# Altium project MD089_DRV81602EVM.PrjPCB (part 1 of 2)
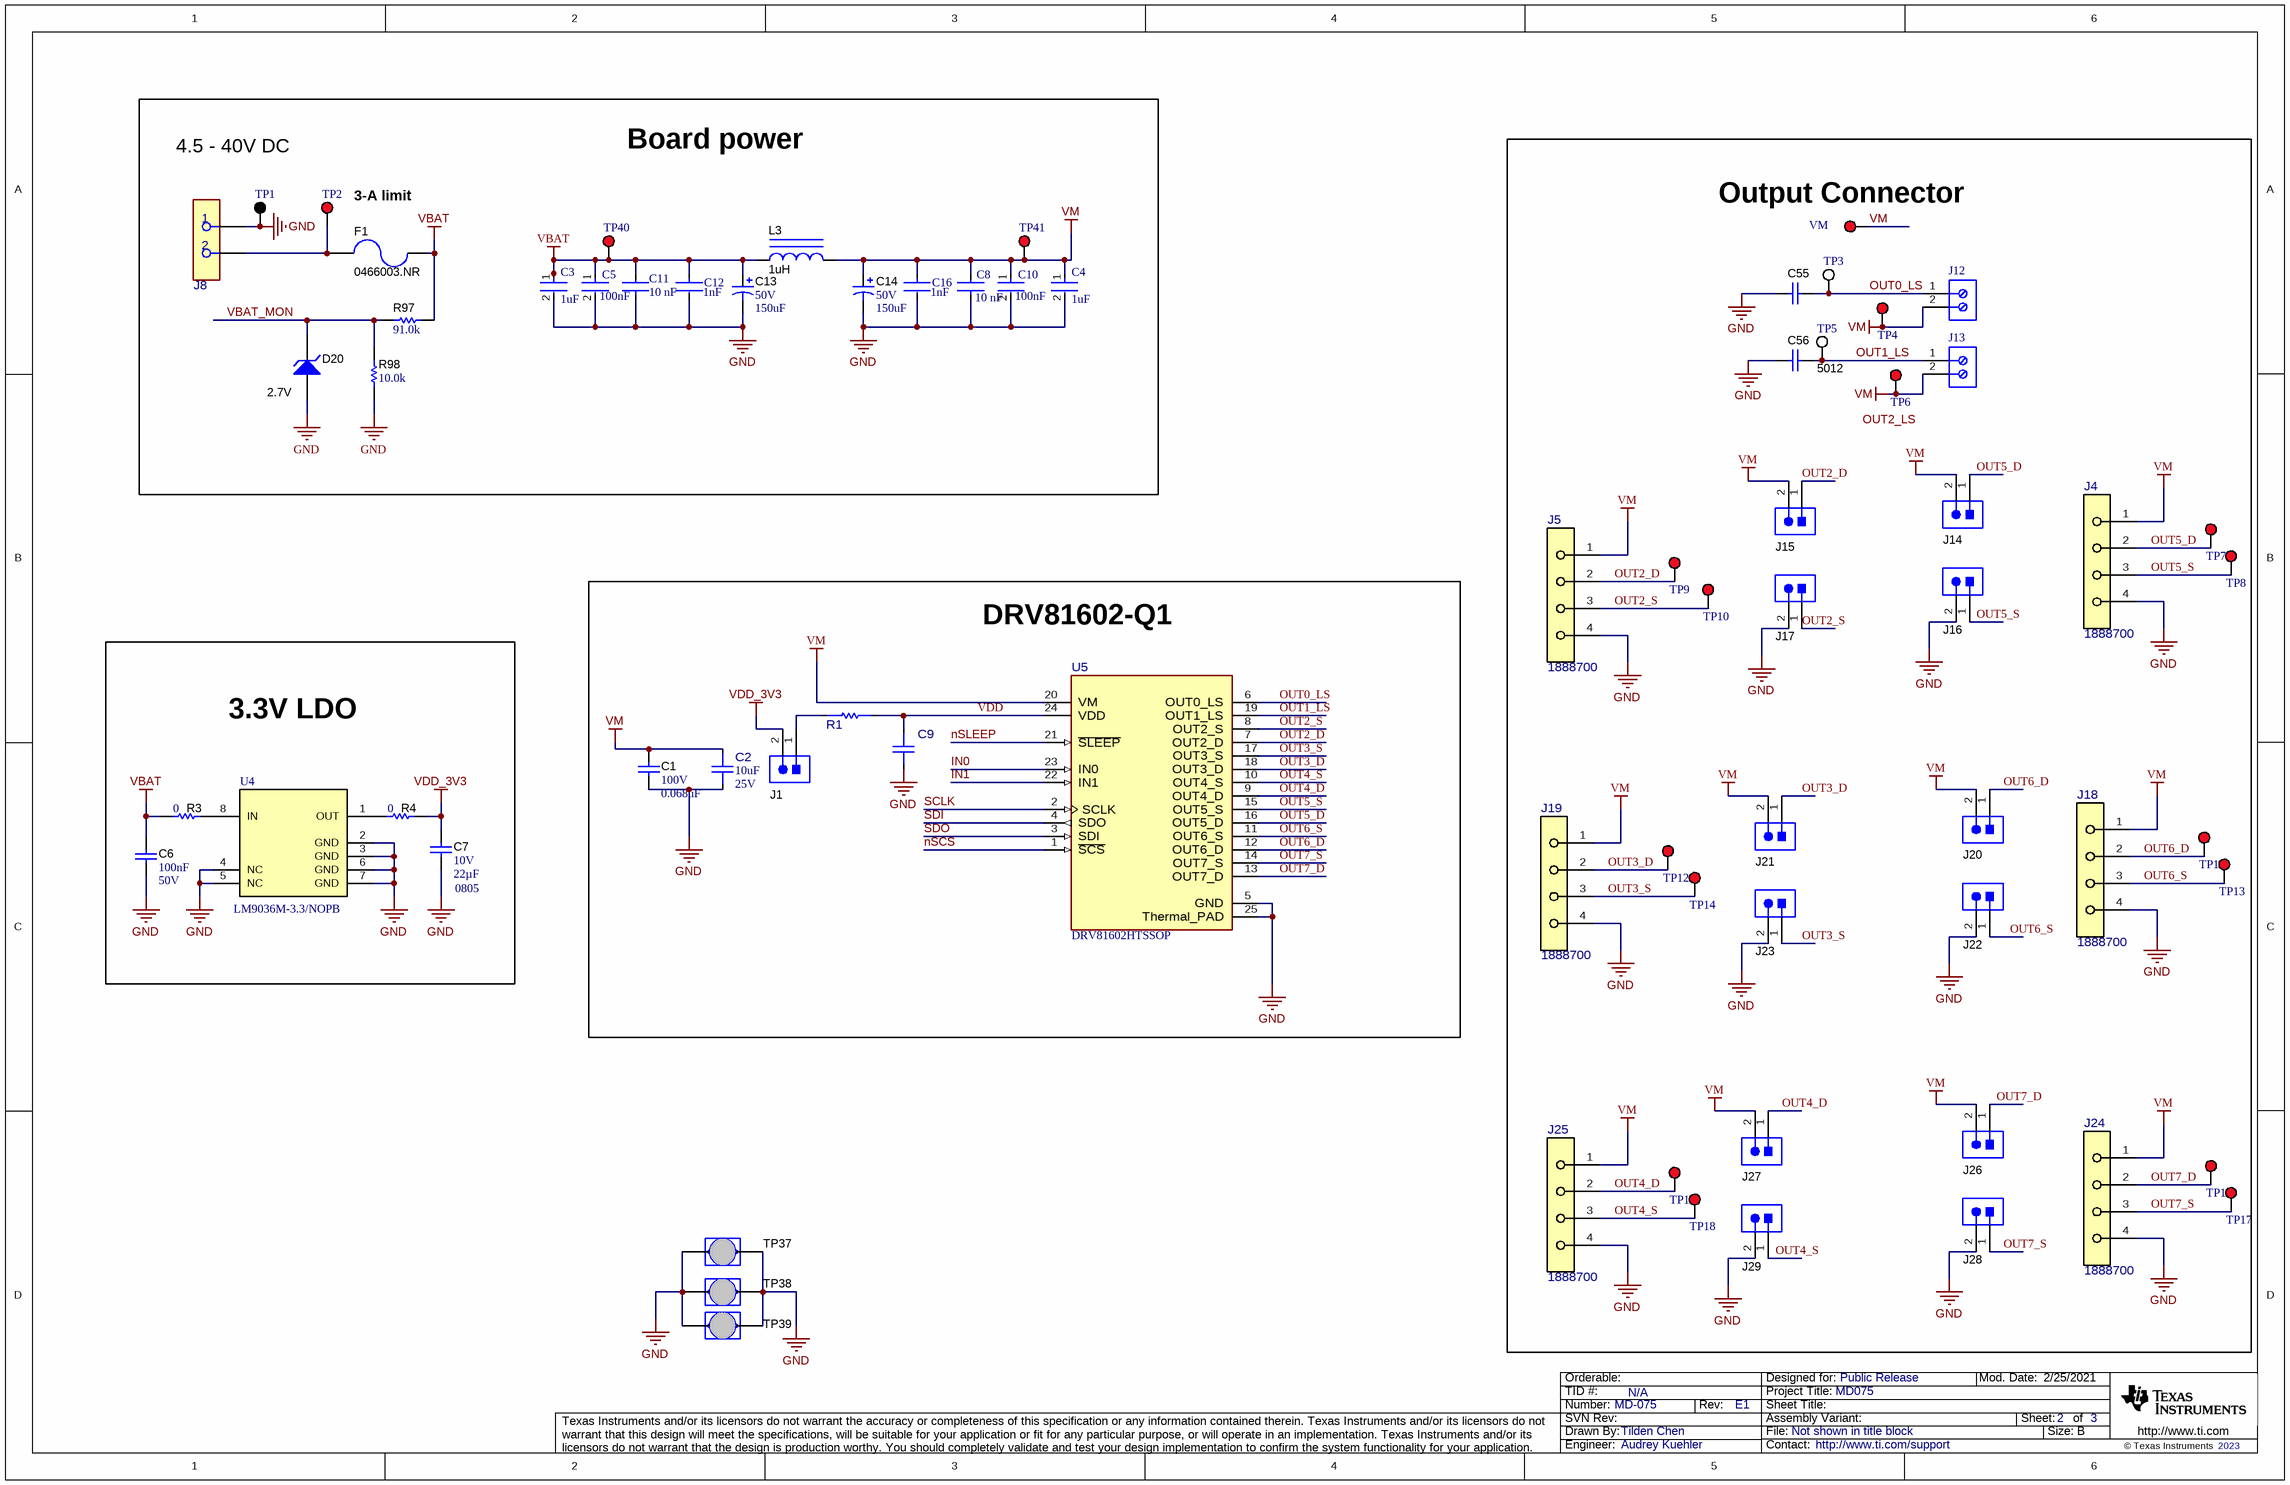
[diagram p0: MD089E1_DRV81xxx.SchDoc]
CopyrightYear: 2023; PCB_Layout: Audrey Kuehler; PCB_Rev: E1; PRJ_Customer: Public Release; PRJ_Engineer: Audrey Kuehler; PRJ_Number: MD-075; PRJ_Title: MD075; SCH_Rev: E1; TechSupport: http://www.ti.com/support; TID: N/A
4 sheets, 256 parts. Net scope: global (net labels, ports and power ports of the same name join across sheets).
Board file: DRV81602Q1_EVM-042624.PcbDoc
Sheets:
  MD089E1_DRV81xxx.SchDoc
  MD089E1_ezFET.SchDoc
  MD089E1_Hardware.SchDoc
  MD089E1_MCU.SchDoc

## Sheet MD089E1_DRV81xxx.SchDoc
size 431 x 279 mm; Date: Not shown in title block; ApprovedBy: Not shown in title block; CheckedBy: Not shown in title block; Author: Not shown in title block; CompanyName: Not shown in title block; DrawnBy: Tilden Chen; Engineer: Not shown in title block; Organization: Not shown in title block; Address1: Not shown in title block; Address2: Not shown in title block; Address3: Not shown in title block; Address4: Not shown in title block; DocumentNumber: 2; Revision: Use project parameter SCH_Rev; SheetNumber: 2; SheetTotal: 3; PageSetup: Record=PageOptions¦CenterHorizontal=True¦CenterVertical=True¦PrintScale=1.00¦XCorrection=1.00¦YCorrection=1.00¦PrintKind=0¦BorderSize=5000000¦LeftOffset=0¦BottomOffset=0¦Orientation=2¦PaperLength=1000¦PaperWidth=1000¦Scale=100¦PaperSource=15¦PrintQuality=600¦MediaType=1¦DitherType=10¦PaperKind=Letter¦PrintScaleMode=1

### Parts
C1  VDC_V: 100V  ValueDisplayed: 0.068uF  [1206]  (hidden comment: 12061C683KAT2A)
C2  ValueDisplayed: 10uF  VDC_V: 25V  [FP-ZRB18AR61E106ME01L_0603-MFG]  (hidden comment: ZRB18AR61E106ME01L)
C3  Capacitance: 1uF  [FP-0603-L_1_6_0_15-W_0_8-IPC_C]  (hidden comment: UMK107AB7105KA-T)
C4  Capacitance: 1uF  [FP-0603-L_1_6_0_15-W_0_8-IPC_C]  (hidden comment: UMK107AB7105KA-T)
C5  value 100nF  [FP-885012206095-MFG]  (hidden comment: 885012206095)
C6  Cap_F: 100nF  VDC_V: 50V  [0603]  (hidden comment: 885012206095)
C7  PackageReference: 0805  VDC_V: 10V  ValueDisplayed: 22µF  [0805_150]  (hidden comment: 885012107011)
C8  value 10 nF  [FP-CC0603-DA-MFG]  (hidden comment: CC0603KPX7R9BB103)
C9  885012205018  [FP-885012205018_0402-MFG]  (value not drawn)
C10  value 100nF  [FP-885012206095-MFG]  (hidden comment: 885012206095)
C11  value 10 nF  [FP-CC0603-DA-MFG]  (hidden comment: CC0603KPX7R9BB103)
C12  1nF  [FP-C0603C-CF-MFG]
C13  VDC_V: 50V  ValueDisplayed: 150uF  [SM_RADIAL_G]  (hidden comment: EEE-FK1H151P)
C14  VDC_V: 50V  ValueDisplayed: 150uF  [SM_RADIAL_G]  (hidden comment: EEE-FK1H151P)
C16  1nF  [FP-C0603C-CF-MFG]
C55  885012206114  [0603]  (value not drawn)
C56  885012206114  [0603]  (value not drawn)
D20  value 2.7V  [SOD-123]  (hidden comment: MMSZ4682-E3-08)
F1  0466003.NR  [1206]
J1  HTSW-102-07-G-S  [Samtec_HTSW-102-07-G-S]  (value not drawn)
J4  1888700  [FP-1888700_HDR4-MFG]
J5  1888700  [FP-1888700_HDR4-MFG]
J8  691250610002  [FP-691250610002_CONN_TERM_BLOCK2-MFG]  (value not drawn)
J12  691101710002  [691101710002]  (value not drawn)
J13  691101710002  [691101710002]  (value not drawn)
J14  HTSW-102-07-G-S  [Samtec_HTSW-102-07-G-S]  (value not drawn)
J15  HTSW-102-07-G-S  [Samtec_HTSW-102-07-G-S]  (value not drawn)
J16  HTSW-102-07-G-S  [Samtec_HTSW-102-07-G-S]  (value not drawn)
J17  HTSW-102-07-G-S  [Samtec_HTSW-102-07-G-S]  (value not drawn)
J18  1888700  [FP-1888700_HDR4-MFG]
J19  1888700  [FP-1888700_HDR4-MFG]
J20  HTSW-102-07-G-S  [Samtec_HTSW-102-07-G-S]  (value not drawn)
J21  HTSW-102-07-G-S  [Samtec_HTSW-102-07-G-S]  (value not drawn)
J22  HTSW-102-07-G-S  [Samtec_HTSW-102-07-G-S]  (value not drawn)
J23  HTSW-102-07-G-S  [Samtec_HTSW-102-07-G-S]  (value not drawn)
J24  1888700  [FP-1888700_HDR4-MFG]
J25  1888700  [FP-1888700_HDR4-MFG]
J26  HTSW-102-07-G-S  [Samtec_HTSW-102-07-G-S]  (value not drawn)
J27  HTSW-102-07-G-S  [Samtec_HTSW-102-07-G-S]  (value not drawn)
J28  HTSW-102-07-G-S  [Samtec_HTSW-102-07-G-S]  (value not drawn)
J29  HTSW-102-07-G-S  [Samtec_HTSW-102-07-G-S]  (value not drawn)
L3  ValueDisplayed: 1uH  [WE-HCC_1210]  (hidden comment: 7443320100)
R1  SG73S1JTTD101J  [FP-SG73S1JTTD101J_0603-MFG]  (value not drawn)
R3  value 0  [0603L]  (hidden comment: Resistor)
R4  value 0  [0603L]  (hidden comment: Resistor)
R97  ValueDisplayed: 91.0k  [0603L]  (hidden comment: RG1608P-913-B-T5)
R98  ValueDisplayed: 10.0k  [0603L]  (hidden comment: RG1608P-103-B-T5)
TP1  5011  [Keystone5011]  (value not drawn)
TP2  5010  [Keystone5010]  (value not drawn)
TP3  5012  [Keystone5012]  (value not drawn)
TP4  5010  [Keystone5010]  (value not drawn)
TP5  5012  [Keystone5012]
TP6  5010  [Keystone5010]  (value not drawn)
TP7  5010  [Keystone5010]  (value not drawn)
TP8  5010  [Keystone5010]  (value not drawn)
TP9  5010  [Keystone5010]  (value not drawn)
TP10  5010  [Keystone5010]  (value not drawn)
TP11  5010  [Keystone5010]  (value not drawn)
TP12  5010  [Keystone5010]  (value not drawn)
TP13  5010  [Keystone5010]  (value not drawn)
TP14  5010  [Keystone5010]  (value not drawn)
TP15  5010  [Keystone5010]  (value not drawn)
TP16  5010  [Keystone5010]  (value not drawn)
TP17  5010  [Keystone5010]  (value not drawn)
TP18  5010  [Keystone5010]  (value not drawn)
TP37  Jumper_2p  [Harwin_D3082-05]  (value not drawn)
TP38  Jumper_2p  [Harwin_D3082-05]  (value not drawn)
TP39  Jumper_2p  [Harwin_D3082-05]  (value not drawn)
TP40  5010  [Keystone5010]  (value not drawn)
TP41  5010  [Keystone5010]  (value not drawn)
U4  LM9036M-3.3/NOPB  [D0008A_N]
U5  DRV81602HTSSOP  [PWP0024T-MFG]
VM  5010  [Keystone5010]  (value not drawn)

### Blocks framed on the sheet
Board power: C3-C5 C8 C10-C14 C16 D20 F1 J8 L3 R97 R98 TP1 TP2 TP40 TP41
Output Connector: C55 C56 J4 J5 J12-J29 TP3-TP18 VM
DRV81602-Q1: C1 C2 C9 J1 R1 U5
3.3V LDO: C6 C7 R3 R4 U4

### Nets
GND: C1.2 C2.2 C3.2 C4.2 C5.2 C6.2 C7.2 C8.1 C9.2 C10.2 C11.1 C12.2 C13.2(-) C14.2(-) C16.2 C55.2 C56.2 D20.2(A) J4.4 J5.4 J8.1 J16.2 J17.2 J18.4 J19.4 J22.2 J23.2 J24.4 J25.4 J28.2 J29.2 R98.1 TP1.1 TP37.1 TP37.2 TP38.1 TP38.2 TP39.1 TP39.2 U4.2(GND) U4.3(GND) U4.4(NC) U4.5(NC) U4.6(GND) U4.7(GND) U5.5(GND) U5.25(Thermal_PAD)
VBAT: C3.1 C5.1 C6.1 C11.2 C12.1 C13.1(+) F1.1 L3.1 R3.2 R97.2 TP40.1  [project net VS]
VDD_3V3: C7.1 J1.2 R4.1
VM: C1.1 C2.1 C4.1 C8.2 C10.1 C14.1(+) C16.1 J4.1 J5.1 J12.2 J13.2 J14.2 J15.2 J18.1 J19.1 J20.2 J21.2 J24.1 J25.1 J26.2 J27.2 L3.2 TP4.1 TP6.1 TP41.1 U5.20(VM) VM.1
IN0: U5.23(IN0)
IN1: U5.22(IN1)
nSCS: U5.1(~{SCS})
nSLEEP: U5.21(~{SLEEP})
OUT0_LS: C55.1 J12.1 TP3.1 U5.6(OUT0_LS)
OUT1_LS: C56.1 J13.1 TP5.1 U5.19(OUT1_LS)
OUT2_D: J5.2 J15.1 TP9.1 U5.7(OUT2_D)
OUT2_S: J5.3 J17.1 TP10.1 U5.8(OUT2_S)
OUT3_D: J19.2 J21.1 TP12.1 U5.18(OUT3_D)
OUT3_S: J19.3 J23.1 TP14.1 U5.17(OUT3_S)
OUT4_D: J25.2 J27.1 TP16.1 U5.9(OUT4_D)
OUT4_S: J25.3 J29.1 TP18.1 U5.10(OUT4_S)
OUT5_D: J4.2 J14.1 TP7.1 U5.16(OUT5_D)
OUT5_S: J4.3 J16.1 TP8.1 U5.15(OUT5_S)
OUT6_D: J18.2 J20.1 TP11.1 U5.12(OUT6_D)
OUT6_S: J18.3 J22.1 TP13.1 U5.11(OUT6_S)
OUT7_D: J24.2 J26.1 TP15.1 U5.13(OUT7_D)
OUT7_S: J24.3 J28.1 TP17.1 U5.14(OUT7_S)
SCLK: U5.2(SCLK)
SDI: U5.4(SDO)
SDO: U5.3(SDI)
VBAT_MON: D20.1(K) R97.1 R98.2
VDD: C9.1 R1.2 U5.24(VDD)
NetF1_2: F1.2 J8.2 TP2.1
NetJ1_1: J1.1 R1.1
NetR3_1: R3.1 U4.8(IN)
NetR4_2: R4.2 U4.1(OUT)

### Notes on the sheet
- 4.5 - 40V DC
- 3-A limit
- Labels drawn without touching a wire or pin: OUT2_LS

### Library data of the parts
C1 = CMP-0008507-2: CAP, CERM, 0.068 uF, 100 V, +/- 10%, X7R, 1206; Manufacturer: AVX; TaMin_C: -55°C; ESR_ohm: 0.045; Polarized: N; SizeAreaWB_mm2: 10.92; Value1: 0.045 ohm; U/M: EA; TaMax_C: 125°C; SizeZ_mm: 1.35; SizeX_mm: 3.2; SizeY_mm: 1.6; SizeArea_mm2: 5.12; Cap_F: 68nF; AEC Category: Q200
C2 = CMP-0094458-1: 10µF ±20% 25V Ceramic Capacitor X5R 0603 (1608 Metric); Manufacturer: Murata Electronics; SizeZ_mm: 1.2mm; AEC Qualified: No
C3 C4 = CMP-2000-07531-4: Ceramic Capacitor General Use 1uF ±10% 50V X7R 0603
C5 C10 = CMP-207839-000004-1: CAP CER 0.1UF 50V X7R 0603; Tolerance: 10%
C6 = CMP-0006837-4: CAP, CERM, 0.1 uF, 50 V, +/- 10%, X7R, 0603; Manufacturer: Wurth Elektronik; TaMin_C: -55°C; Polarized: N; SizeAreaWB_mm2: 4.68; Value1: Unknown; U/M: EA; Value: 0.1uF; TaMax_C: 125°C; SizeZ_mm: 1; SizeX_mm: 1.6; SizeY_mm: 0.8; SizeArea_mm2: 1.28; AEC Category: Q200
C7 = CMP-0078153-1: CAP, CERM, 22 µF, 10 V,+/- 20%, X5R, 0805; Manufacturer: Wurth Elektronik; TaMin_C: -55°C; Polarized: N; SizeAreaWB_mm2: 6.75; U/M: EA; Value: 22uF; TaMax_C: 85°C; SizeZ_mm: 1.5; SizeX_mm: 2; SizeY_mm: 1.25; SizeArea_mm2: 2.5; AEC Category: Q200
C8 C11 = CMP-1035-02321-3: CAP CER 10000PF 50V X7R 0603; Manufacturer: YAGEO; Alternative PartNumber: 885382206002; Alternative Manufacturer: Wurth Elektronik; Tolerance: 0.1; Material: Ceramic; Temperature Coefficient: 15%
C9 = CMP-0090362-1: 0.1µF ±10% 10V Ceramic Capacitor X7R 0402 (1005 Metric); Manufacturer: Wurth Electronics; AEC Qualified: No; Value: 100nF; SizeZ_mm: 0.55mm; ValueDisplayed: 100000pF; TempCo: 15%
C12 C16 = CMP-03020-030804-1: CAP CER 1000PF 50V X7R 0603; Manufacturer Part Number: C0603C102J5RACAUTO; Manufacturer: KEMET; Alternate PartNumber: 885012206083; Alternate Manufacturer: Wurth Elektronik; Material: Ceramic; Value: 1,000 pF; Temperature Coefficient: 30ppm/°C; Automotive Grade: Grade 1; Tolerance: 0.05
C13 C14 = CMP-0011178-2: CAP, AL, 150 uF, 50 V, +/- 20%, 0.18 ohm, AEC-Q200 Grade 2, SMD; Manufacturer: Panasonic; Alternate Manufacturer: Wurth Elektronik; Alternate PartNumber: 865080657017; TaMin_C: -55°C; ESR_ohm: 0.18; Polarized: Y; SizeAreaWB_mm2: 172.2; U/M: EA; Value: 150uF; TaMax_C: 105°C; SizeZ_mm: 10.2; SizeX_mm: 12; SizeY_mm: 10.3; Cap_Case: G; SizeArea_mm2: 123.6; CompType: Capacitor; Cap_F: 150µF; IRMS_A: 670mA; AEC Grade: 2; AEC Category: Q200
C55 C56 = CMP-0079993-1: CAP, CERM, 0.01 µF, 100 V,+/- 10%, X7R, 0603; Manufacturer: Wurth Elektronik; TaMin_C: -55°C; Polarized: N; SizeAreaWB_mm2: 4.68; U/M: EA; Value: 0.01uF; TaMax_C: 105°C; SizeZ_mm: 1; SizeX_mm: 1.6; SizeY_mm: 0.8; Value2: 100V; SizeArea_mm2: 1.28; Cap_F: 10nF; AEC Category: Q200; ValueDisplayed: 0.01µF
D20 = CMP-0077592-3: Diode, Zener, 2.7 V, 500 mW, SOD-123; Manufacturer: Vishay-Semiconductor; AEC Category: Q101; AEC Qualified: N; SizeAreaWB_mm2: 13.095; SizeY_mm: 1.7; SizeX_mm: 3.85; Value1: 0.5W; SizeArea_mm2: 6.545; SizeZ_mm: 1.35; RJA_CperW: 340; Power_W: 500mW
F1 = CMP-0084439-1: Fuse, 3 A, 32VAC/VDC, SMD; Manufacturer: Littelfuse; VAC_V: 32V; Rtyp_Ohm: 0.019; Interrupt_AC: 50A; MeltingTyp: 0.576; SizeX_mm: 3.2; Fuse Technology: Board Mount; Irating_A: 3A; SizeAreaWB_mm2: 10.92; TaMin_C: -55°C; Fuse Speed: Fast; SizeArea_mm2: 5.12; SizeY_mm: 1.6; SizeZ_mm: 1.35; TaMax_C: 90°C
J1 J14-J17 J20-J23 J26-J29 = CMP-0075483-1: Header, 100mil, 2x1, Gold, TH; Manufacturer: Samtec; Green_REACh: Passed; CT: False; Green_Lifecycle: Active; CNHeader: True
J4 J5 J18 J19 J24 J25 = CMP-0086377-1: Conn; Term Blk; PCB; Screw; 4; 5.08 mm; Front; 24-14 AWG; 16 A; 250 V; Solder; Manufacturer: Phoenix Contact; ContactFinish: Tin; Current_A: 16A; Row_Count: 1; Voltage_V: 400V
J8 = CMP-0093233-2: 2 Position Wire to Board Terminal Block Horizontal with Board 0.250" (6.35mm) Through Hole; Manufacturer: Wurth Electronics; Current_A: 32A; Conn Gender: Female; Row_Count: 1; ContactFinish: Zinc; SizeZ_mm: 21.6mm; Max Wire Gauge: 10; Min Wire Gauge: 30; Voltage_V: 450V; AEC Qualified: No; Is Female: yes
J12 J13 = CMP-1502-03256-1: Series 101 - 5.00 mm Horizontal Entry Modular with Pressure Clamp WR-TBL, 2 pin; Manufacturer: Wurth Elektronik; Pin Number: 2; Pitch: 5.00mm
L3 = CMP-0063986-1: Inductor, Shielded Drum Core, Ferrite, 1 uH, 24 A, 0.0012 ohm, SMD; Manufacturer: Wurth Elektronik; Isat: 32A @ 30% inductance drop; Irms: 24A @ 50C rise; Green_Lifecycle: Active; SizeAreaWB_mm2: 188.94; DCR_ohm: 1.2m; Green_REACh: Passed; Value: 1uH; Imax_A: 24A; SizeZ_mm: 10; SizeX_mm: 12.1; SizeY_mm: 11.4; SizeArea_mm2: 137.94; Ind_H: 1µH; AEC Category: Q200
R1 = CMP-0095262-1: 100 Ohms ±5% 0.2W, 1/5W Chip Resistor 0603 (1608 Metric) Automotive AEC-Q200, Moisture Resistant, Pulse Withstanding Thick Film; Manufacturer: KOA Speer; AEC Qualified: Yes; Value: 100; AEC Grade: Grade 0; VDC_V: 150V; TaMax_C: +70°C; TempCo: 100ppm/°C; Power_W: 200mW; SizeZ_mm: 0.55mm
R3 R4 = CMP-0025697-4: RES, 0, 5%, 0.1 W, AEC-Q200 Grade 0, 0603; PartNumber: CRCW06030000Z0EA; Manufacturer: Vishay-Dale; Value_Code: 0000; Power_W: 100mW; Value2: 0.1W; VDC_V: 75V; TempCo: 200 ppm/C; EIA_Code: E24; AEC Category: Q200; AEC Qualified: Y; SizeArea_mm2: 1.28; SizeX_mm: 1.6; SizeY_mm: 0.8; SizeZ_mm: 1
R97 = CMP-0023620-3: RES, 91.0 k, 0.1%, 0.1 W, 0603; Manufacturer: Susumu Co Ltd; Power_W: 100mW; TempCo: 25 ppm/C; Value_Code: 91k0; U/M: EA; Value: 91.0k; Res_ohm: 91k; SizeX_mm: 1.6; SizeY_mm: 0.8; SizeZ_mm: 1; Value2: 0.1W; SizeArea_mm2: 1.28; VDC_V: 75V; AEC Category: Q200
R98 = CMP-0023404-3: RES, 10.0 k, 0.1%, 0.1 W, 0603; Manufacturer: Susumu Co Ltd; Power_W: 100mW; TempCo: 25 ppm/C; Value_Code: 10k0; U/M: EA; Value: 10.0k; EIA_Code: E192; Res_ohm: 10k; SizeX_mm: 1.6; SizeY_mm: 0.8; SizeZ_mm: 1; Value2: 0.1W; SizeArea_mm2: 1.28; VDC_V: 75V; AEC Category: Q200
TP1 = CMP-0055148-2: Test Point, Multipurpose, Black, TH; Manufacturer: Keystone Electronics; CNHeader: FALSE; Green_Lifecycle: Active; Green_REACh: Passed; ContactFinish: Silver; CT: TRUE
TP2 TP4 TP6-TP18 VM = CMP-0055147-2: Test Point, Multipurpose, Red, TH; Manufacturer: Keystone Electronics; CNHeader: FALSE; Green_Lifecycle: Active; Green_REACh: Passed; ContactFinish: Silver; CT: TRUE
TP3 TP5 = CMP-0055149-2: Test Point, Multipurpose, White, TH; Manufacturer: Keystone Electronics; ContactFinish: Silver; CT: TRUE; CNHeader: FALSE; Green_Lifecycle: Active; Green_REACh: Passed
TP37-TP39 = CMP-0075110-1: 1mm Uninsulated Shorting Plug, 10.16mm spacing, TH; Manufacturer: Harwin; PartNumber: D3082-05; CompType: Jumper Wire; CNHeader: False; Green_Lifecycle: Active; Green_REACh: Passed
TP40 TP41 = CMP-0055147-1: Test Point, Multipurpose, Red, TH; Manufacturer: Keystone; CNHeader: FALSE; Green_Lifecycle: Active; Green_REACh: Passed; ContactFinish: Silver; CT: TRUE
U4 = CMP-0070570-1: Ultra-Low Quiescent Current Voltage Regulator, 8-pin Narrow SOIC, Pb-Free; Manufacturer: Texas Instruments; PackageTopMarking: NSZXTT*LM903*6M-3; PowerWise: N; CompType: LDO IC
U5 = CMP-0120420-1: 8-channel Configurable Low-side and High-side Driver for Automotive Relay, Lighting and Motor Control; Manufacturer: Texas Instruments; SizeZ_mm: 1.2mm; AEC Qualified: No; Max Supply Voltage: 40V; Min Supply Voltage: 3V; Number Of Outputs: 8; Standoff Height: 0.05mm; TaMax_C: +125°C; TaMin_C: -40°C; TJmax_C: +150°C

## Sheet MD089E1_ezFET.SchDoc
size 431 x 279 mm; Date: Not shown in title block; ApprovedBy: Not shown in title block; CheckedBy: Not shown in title block; Author: Not shown in title block; CompanyName: Not shown in title block; DrawnBy: Murugavel Raju; Engineer: Not shown in title block; Organization: Not shown in title block; Address1: Not shown in title block; Address2: Not shown in title block; Address3: Not shown in title block; Address4: Not shown in title block; DocumentNumber: 1; Revision: Use project parameter SCH_Rev; SheetNumber: 1; SheetTotal: 3; PageSetup: Record=PageOptions¦CenterHorizontal=True¦CenterVertical=True¦PrintScale=1.00¦XCorrection=1.00¦YCorrection=1.00¦PrintKind=0¦BorderSize=5000000¦LeftOffset=0¦BottomOffset=0¦Orientation=2¦PaperLength=1000¦PaperWidth=1000¦Scale=100¦PaperSource=15¦PrintQuality=600¦MediaType=1¦DitherType=10¦PaperKind=Letter¦PrintScaleMode=1
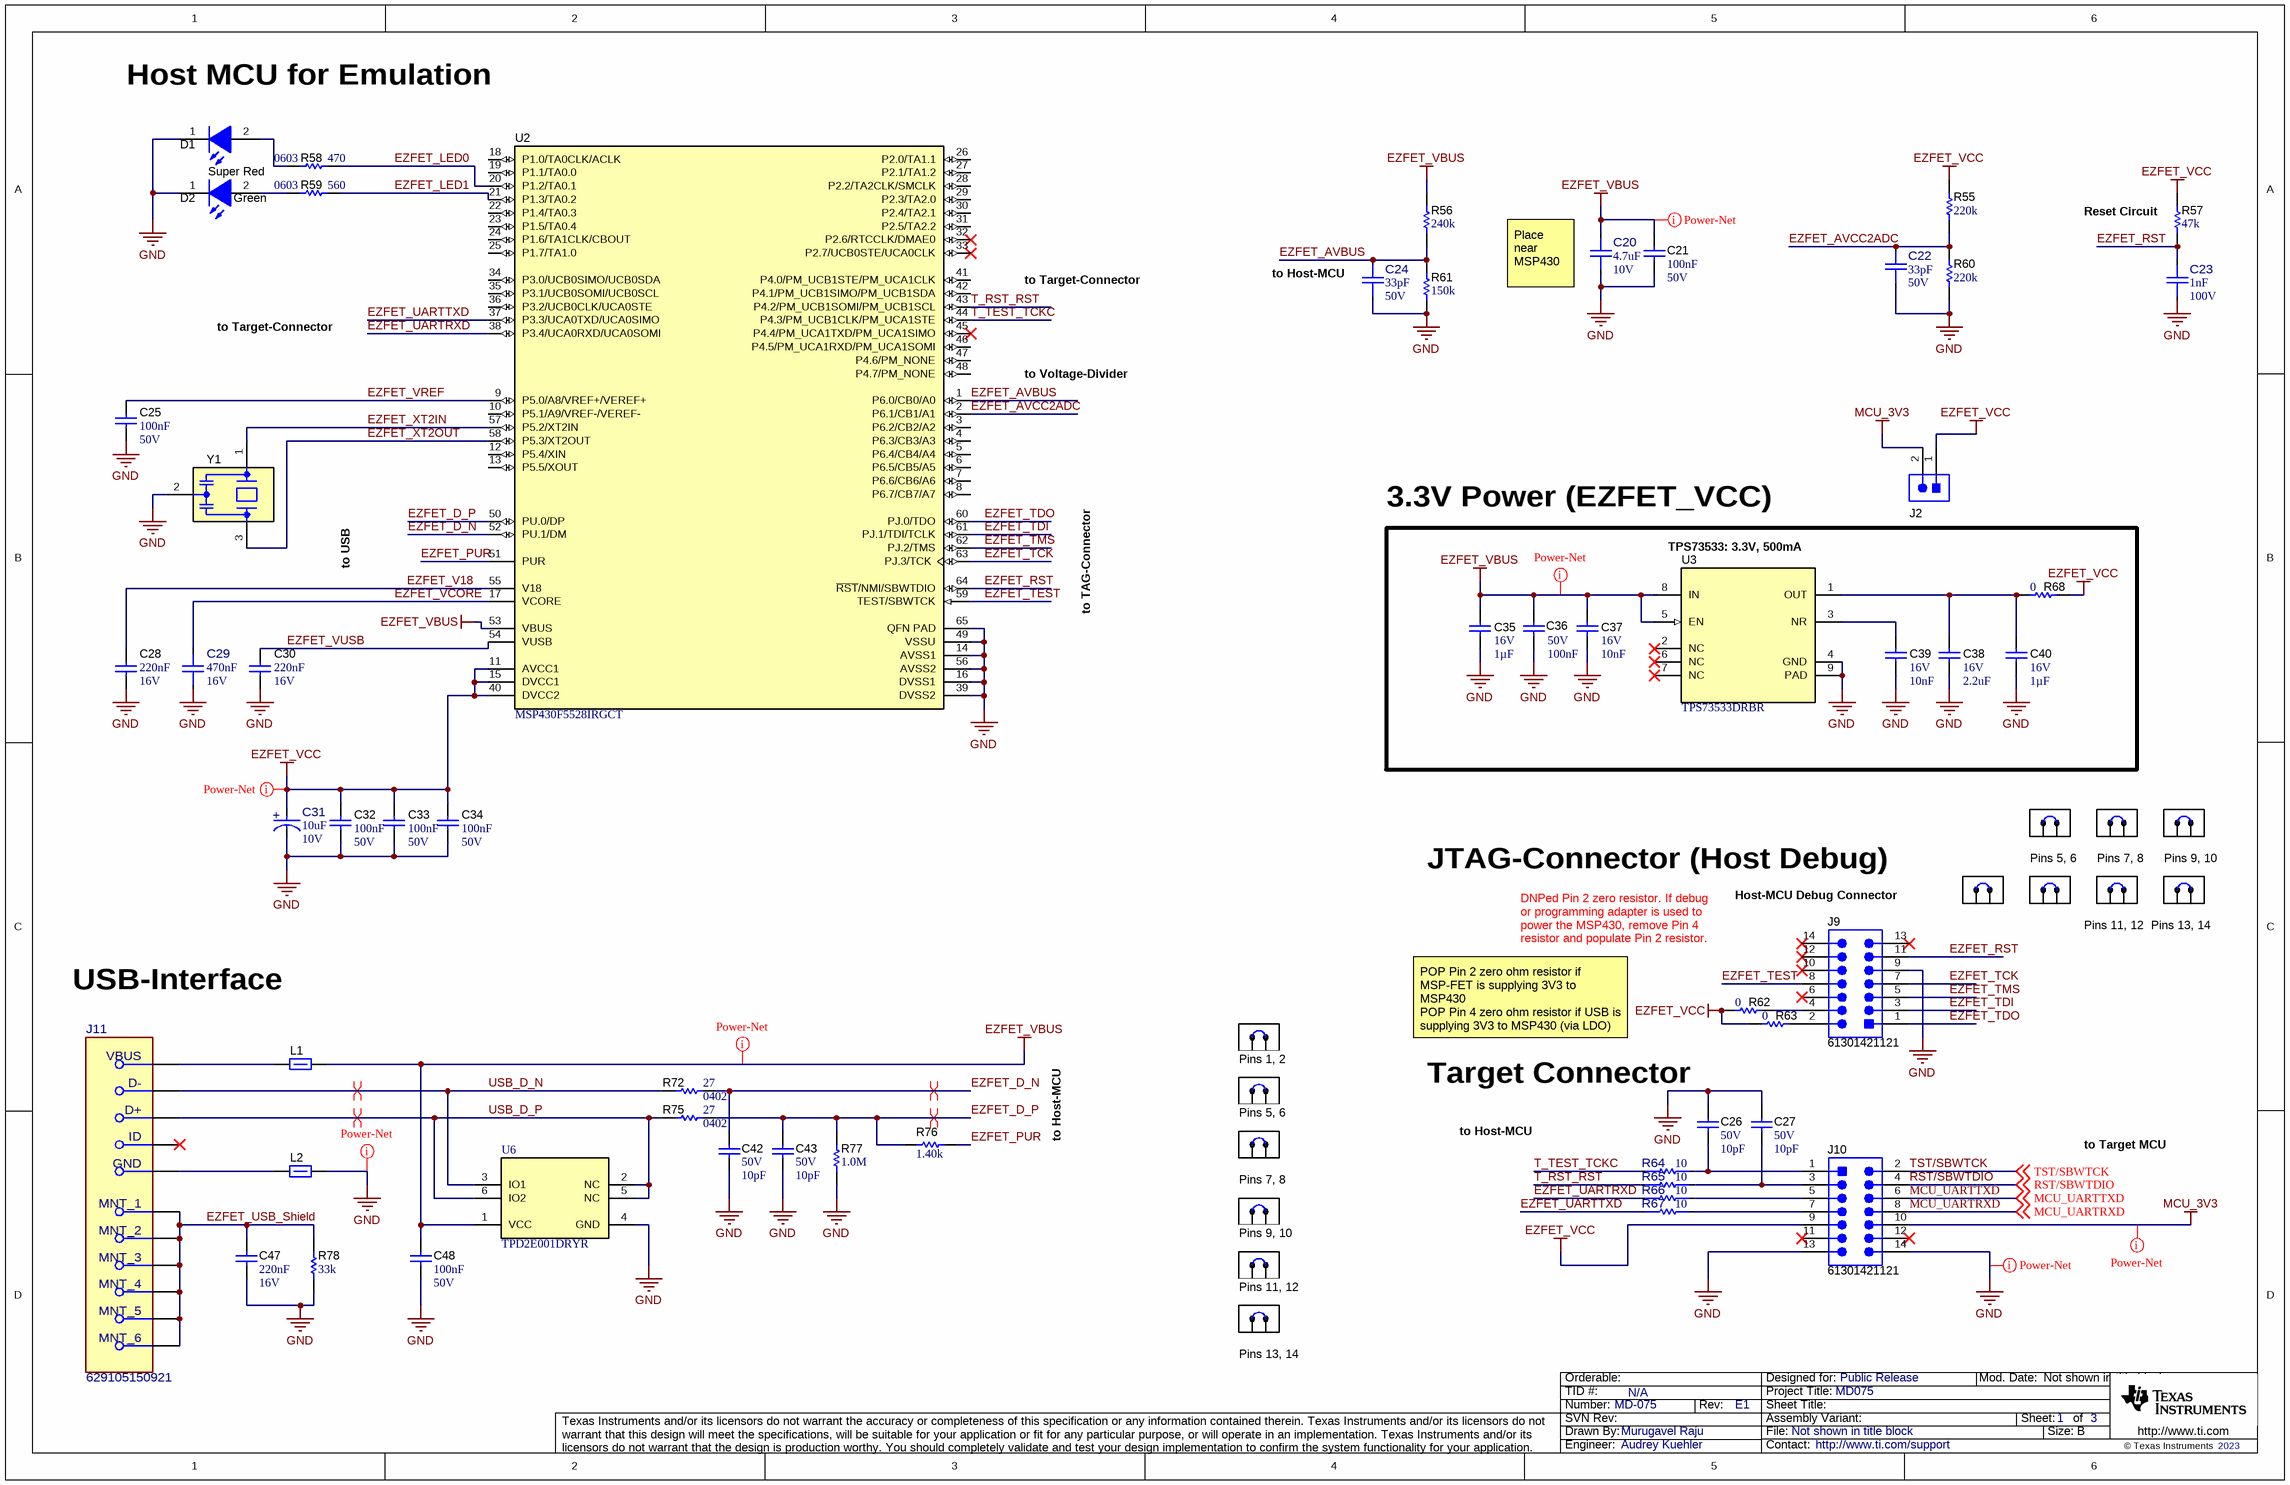
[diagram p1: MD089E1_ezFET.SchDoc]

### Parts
C20  ValueDisplayed: 4.7uF  VDC_V: 10V  [FP-885012106012_0603-MFG]  (hidden comment: 885012106012)
C21  Cap_F: 100nF  VDC_V: 50V  [0603]  (hidden comment: 885012206095)
C22  ValueDisplayed: 33pF  VDC_V: 50V  [FP-885012005058_0402-MFG]  (hidden comment: 885012005058)
C23  ValueDisplayed: 1nF  VDC_V: 100V  [FP-885012006085_0603-MFG]  (hidden comment: 885012006085)
C24  ValueDisplayed: 33pF  VDC_V: 50V  [FP-885012005058_0402-MFG]  (hidden comment: 885012005058)
C25  Cap_F: 100nF  VDC_V: 50V  [0603]  (hidden comment: 885012206095)
C26  VDC_V: 50V  ValueDisplayed: 10pF  [0402]  (hidden comment: 885012005055)
C27  VDC_V: 50V  ValueDisplayed: 10pF  [0402]  (hidden comment: 885012005055)
C28  Cap_F: 220nF  VDC_V: 16V  [0603L]  (hidden comment: 885012206048)
C29  VDC_V: 16V  Cap_F: 470nF  [FP-885012206050_0603-MFG]  (hidden comment: 885012206050)
C30  Cap_F: 220nF  VDC_V: 16V  [0603L]  (hidden comment: 885012206048)
C31  ValueDisplayed: 10uF  VDC_V: 10V  [FP-875105240001_SMT_CAP_4MM3_4MM3-MFG]  (hidden comment: 875105240001)
C32  Cap_F: 100nF  VDC_V: 50V  [0603]  (hidden comment: 885012206095)
C33  Cap_F: 100nF  VDC_V: 50V  [0603]  (hidden comment: 885012206095)
C34  Cap_F: 100nF  VDC_V: 50V  [0603]  (hidden comment: 885012206095)
C35  Cap_F: 1µF  VDC_V: 16V  [0603]  (hidden comment: 885012206052)
C36  Cap_F: 100nF  VDC_V: 50V  [0603]  (hidden comment: 885012206095)
C37  Cap_F: 10nF  VDC_V: 16V  [0603]  (hidden comment: 885012206040)
C38  VDC_V: 16V  ValueDisplayed: 2.2uF  [0603]  (hidden comment: 885012106018)
C39  Cap_F: 10nF  VDC_V: 16V  [0603]  (hidden comment: 885012206040)
C40  Cap_F: 1µF  VDC_V: 16V  [0603]  (hidden comment: 885012206052)
C42  VDC_V: 50V  ValueDisplayed: 10pF  [0402]  (hidden comment: 885012005055)
C43  VDC_V: 50V  ValueDisplayed: 10pF  [0402]  (hidden comment: 885012005055)
C47  Cap_F: 220nF  VDC_V: 16V  [0603L]  (hidden comment: 885012206048)
C48  Cap_F: 100nF  VDC_V: 50V  [0603]  (hidden comment: 885012206095)
D1  value Super Red  [WL-SMCW_RED]  (hidden comment: 150060SS75000)
D2  value Green  [WL-SMCW_GREEN]  (hidden comment: 150060VS75000)
J2  HTSW-102-07-G-S  [Samtec_HTSW-102-07-G-S]  (value not drawn)
J9  61301421121  [Wurth_61301421121]
J10  61301421121  [Wurth_61301421121]
J11  629105150921  [FP-629105150921_CONN_PTH_USB_8MM0_5MM6-MFG]
L1  742792621  [0603L]  (value not drawn)
L2  742792621  [0603L]  (value not drawn)
R55  ValueDisplayed: 220k  [0402]  (hidden comment: RC0402FR-07220KL)
R56  ValueDisplayed: 240k  [0402]  (hidden comment: CRCW0402240KFKED)
R57  ValueDisplayed: 47k  [0402]  (hidden comment: CRCW040247K0JNED)
R58  ValueDisplayed: 470  [0603]  (hidden comment: RC0603JR-07470RL)
R59  ValueDisplayed: 560  [0603]  (hidden comment: RC0603JR-07560RL)
R60  ValueDisplayed: 220k  [0402]  (hidden comment: RC0402FR-07220KL)
R61  ValueDisplayed: 150k  [0402]  (hidden comment: CRCW0402150KFKED)
R62  value 0  [0603L]  (hidden comment: Resistor)
R63  value 0  [0603L]  (hidden comment: Resistor)
R64  value 10  [FP-560050310009_0402-MFG]  (hidden comment: 560050310009)
R65  value 10  [FP-560050310009_0402-MFG]  (hidden comment: 560050310009)
R66  value 10  [FP-560050310009_0402-MFG]  (hidden comment: 560050310009)
R67  value 10  [FP-560050310009_0402-MFG]  (hidden comment: 560050310009)
R68  value 0  [0603L]  (hidden comment: Resistor)
R72  PackageReference: 0402  ValueDisplayed: 27  [0402L]  (hidden comment: CRCW040227R0JNED)
R75  PackageReference: 0402  ValueDisplayed: 27  [0402L]  (hidden comment: CRCW040227R0JNED)
R76  ValueDisplayed: 1.40k  [0402L]  (hidden comment: CRCW04021K40FKED)
R77  ValueDisplayed: 1.0M  [0402L]  (hidden comment: CRCW04021M00JNED)
R78  ValueDisplayed: 33k  [0402S]  (hidden comment: CRCW040233K0JNED)
SH-J22  60900213421  [Wurth_60900213421]  (value not drawn)
SH-J23  60900213421  [Wurth_60900213421]  (value not drawn)
SH-J24  60900213421  [Wurth_60900213421]  (value not drawn)
SH-J25  60900213421  [Wurth_60900213421]  (value not drawn)
SH-J26  60900213421  [Wurth_60900213421]  (value not drawn)
SH-J27  60900213421  [Wurth_60900213421]  (value not drawn)
SH-J28  60900213421  [Wurth_60900213421]  (value not drawn)
SH-J29  60900213421  [Wurth_60900213421]  (value not drawn)
SH-J31  60900213421  [Wurth_60900213421]  (value not drawn)
SH-J32  60900213421  [Wurth_60900213421]  (value not drawn)
SH-J33  60900213421  [Wurth_60900213421]  (value not drawn)
SH-J34  60900213421  [Wurth_60900213421]  (value not drawn)
SH-J35  60900213421  [Wurth_60900213421]  (value not drawn)
U2  MSP430F5528IRGCT  [RGC0064B]
U3  TPS73533DRBR  [DRB0008A]
U6  TPD2E001DRYR  [DRY0006A]
Y1  CSTNR4M00GH5L000R0  [MuRata_CSTNR]  (value not drawn)

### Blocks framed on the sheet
3.3V Power (EZFET_VCC): C35-C40 R68 U3

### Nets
EZFET_VBUS: C20.2 C21.1 C35.1 C36.1 C37.1 C48.2 L1.2 R56.2 U2.53(VBUS) U3.5(EN) U3.8(IN) U6.1(VCC)
EZFET_VCC: C31.2(ANODE) C32.1 C33.1 C34.1 J2.1 J10.9 R55.2 R57.2 R62.2 R63.2 R68.1 U2.11(AVCC1) U2.15(DVCC1) U2.40(DVCC2)
GND: C20.1 C21.2 C22.1 C23.1 C24.1 C25.2 C26.1 C27.1 C28.2 C29.1 C30.2 C31.1(CATHODE) C32.2 C33.2 C34.2 C35.2 C36.2 C37.2 C38.2 C39.2 C40.2 C42.2 C43.2 C47.2 C48.1 D1.1(K) D2.1(K) J9.9 J10.13 J10.14 L2.2 R60.1 R61.1 R77.1 R78.1 U2.14(AVSS1) U2.16(DVSS1) U2.39(DVSS2) U2.49(VSSU) U2.56(AVSS2) U2.65(QFN_PAD) U3.4(GND) U3.9(PAD) U6.4(GND) Y1.2(GND)
MCU_3V3: J2.2 J10.10
EZFET_AVBUS: C24.2 R56.1 R61.2 U2.1(P6.0/CB0/A0)
EZFET_AVCC2ADC: C22.2 R55.1 R60.2 U2.2(P6.1/CB1/A1)
EZFET_D_N: C42.1 R72.2 U2.52(PU.1/DM)
EZFET_D_P: C43.1 R75.2 R76.1 R77.2 U2.50(PU.0/DP)
EZFET_LED0: R58.1 U2.20(P1.2/TA0.1)
EZFET_LED1: R59.1 U2.21(P1.3/TA0.2)
EZFET_PUR: R76.2 U2.51(PUR)
EZFET_RST: C23.2 J9.11 R57.1 U2.64(~{RST}/NMI/SBWTDIO)
EZFET_TCK: J9.7 U2.63(PJ.3/TCK)
EZFET_TDI: J9.3 U2.61(PJ.1/TDI/TCLK)
EZFET_TDO: J9.1 U2.60(PJ.0/TDO)
EZFET_TEST: J9.8 U2.59(TEST/SBWTCK)
EZFET_TMS: J9.5 U2.62(PJ.2/TMS)
EZFET_UARTRXD: R66.1 U2.38(P3.4/UCA0RXD/UCA0SOMI)
EZFET_UARTTXD: R67.1 U2.37(P3.3/UCA0TXD/UCA0SIMO)
EZFET_USB_Shield: C47.1 J11.6(MNT_1) J11.7(MNT_2) J11.8(MNT_3) J11.9(MNT_4) J11.10(MNT_5) J11.11(MNT_6) R78.2
EZFET_V18: C28.1 U2.55(V18)
EZFET_VCORE: C29.2 U2.17(VCORE)
EZFET_VREF: C25.1 U2.9(P5.0/A8/VREF+/VEREF+)
EZFET_VUSB: C30.1 U2.54(VUSB)
EZFET_XT2IN: U2.57(P5.2/XT2IN) Y1.1(In)
EZFET_XT2OUT: U2.58(P5.3/XT2OUT) Y1.3(Out)
MCU_UARTRXD: J10.8 ; off-sheet MCU_UARTRXD
MCU_UARTTXD: J10.6 ; off-sheet MCU_UARTTXD
RST/SBWTDIO: J10.4 ; off-sheet RST/SBWTDIO
T_RST_RST: R65.1 U2.43(P4.2/PM_UCB1SOMI/PM_UCB1SCL)
T_TEST_TCKC: R64.1 U2.44(P4.3/PM_UCB1CLK/PM_UCA1STE)
TST/SBWTCK: J10.2 ; off-sheet TST/SBWTCK
USB_D_N: J11.2(D-) R72.1 U6.3(IO1)
USB_D_P: J11.3(D+) R75.1 U6.2(NC) U6.5(NC) U6.6(IO2)
NetC26_2: C26.2 J10.1 R64.2
NetC27_2: C27.2 J10.3 R65.2
NetC38_1: C38.1 C40.1 R68.2 U3.1(OUT)
NetC39_1: C39.1 U3.3(NR)
NetD1_2: D1.2(A) R58.2
NetD2_2: D2.2(A) R59.2
NetJ9_2: J9.2 R63.1
NetJ9_4: J9.4 R62.1
NetJ10_5: J10.5 R66.2
NetJ10_7: J10.7 R67.2
NetJ11_1: J11.1(VBUS) L1.1
NetJ11_5: J11.5(GND) L2.1

Not connected (* = marked no-connect by the designer): J9 6* 10* 12* 13* 14*; J10 11* 12*; J11 4(ID)*; U2 3(P6.2/CB2/A2) 4(P6.3/CB3/A3) 5(P6.4/CB4/A4) 6(P6.5/CB5/A5) 7(P6.6/CB6/A6) 8(P6.7/CB7/A7) 10(P5.1/A9/VREF-/VEREF-) 12(P5.4/XIN) 13(P5.5/XOUT) 18(P1.0/TA0CLK/ACLK) 19(P1.1/TA0.0) 22(P1.4/TA0.3) 23(P1.5/TA0.4) 24(P1.6/TA1CLK/CBOUT) 25(P1.7/TA1.0) 26(P2.0/TA1.1) 27(P2.1/TA1.2) 28(P2.2/TA2CLK/SMCLK) 29(P2.3/TA2.0) 30(P2.4/TA2.1) 31(P2.5/TA2.2) 32(P2.6/RTCCLK/DMAE0)* 33(P2.7/UCB0STE/UCA0CLK)* 34(P3.0/UCB0SIMO/UCB0SDA) 35(P3.1/UCB0SOMI/UCB0SCL) 36(P3.2/UCB0CLK/UCA0STE) 41(P4.0/PM_UCB1STE/PM_UCA1CLK) 42(P4.1/PM_UCB1SIMO/PM_UCB1SDA) 45(P4.4/PM_UCA1TXD/PM_UCA1SIMO)* 46(P4.5/PM_UCA1RXD/PM_UCA1SOMI) 47(P4.6/PM_NONE) 48(P4.7/PM_NONE); U3 2(NC)* 6(NC)* 7(NC)*

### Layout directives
net class Power-Net: EZFET_VBUS, EZFET_VCC, GND, MCU_3V3
differential pair: EZFET_D_N, EZFET_D_P, USB_D_N, USB_D_P

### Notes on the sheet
- Host MCU for Emulation
- (near R57) Reset Circuit
- to Target-Connector
- (near C24) to Host-MCU
- (near C20) Place near MSP430
- to Voltage-Divider
- to USB
- to TAG-Connector
- (near U3) TPS73533: 3.3V, 500mA
- JTAG-Connector (Host Debug)
- (near J9) Host-MCU Debug Connector
- (near SH-J23) Pins 5, 6
- (near SH-J27) Pins 7, 8
- (near SH-J28) Pins 9, 10
- DNPed Pin 2 zero resistor. If debug or programming adapter is used to power the MSP430, remove Pin 4 resistor and populate Pin 2 resistor.
- Pins 11, 12
- Pins 13, 14
- USB-Interface
- POP Pin 2 zero ohm resistor if MSP-FET is supplying 3V3 to MSP430
  POP Pin 4 zero ohm resistor if USB is supplying 3V3 to MSP430 (via LDO)
- to Host-MCU
- (near SH-J29) Pins 1, 2
- Target Connector
- (near SH-J31) Pins 5, 6
- to Target MCU
- Pins 7, 8
- (near SH-J33) Pins 9, 10
- (near SH-J34) Pins 11, 12
- (near SH-J35) Pins 13, 14

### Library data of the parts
C20 = CMP-0097305-1: 4.7 µF ±20% 10V Ceramic Capacitor X5R 0603 (1608 Metric); Manufacturer: Wurth Electronics; Cap_F: 4.7µF; Value: 4.7µF; AEC Qualified: No; SizeZ_mm: 0.87mm; TempCo: 15%
C21 C25 C32-C34 C36 C48 = CMP-0006837-4: as C6 on sheet MD089E1_DRV81xxx
C22 C24 = CMP-0097306-1: 33 pF ±5% 50V Ceramic Capacitor C0G, NP0 0402 (1005 Metric); Manufacturer: Wurth Electronics; AEC Qualified: No; Value: 33pF; TempCo: 30ppm/°C; SizeZ_mm: 0.55mm
C23 = CMP-0097311-1: 1000 pF ±5% 100V Ceramic Capacitor C0G, NP0 0603 (1608 Metric); Manufacturer: Wurth Electronics; TempCo: 30ppm/°C; SizeZ_mm: 0.87mm; AEC Qualified: No; Value: 1nF
C26 C27 C42 C43 = CMP-0006215-2: CAP, CERM, 10 pF, 50 V, +/- 5%, C0G/NP0, 0402; Manufacturer: Wurth Elektronik; TaMin_C: -55°C; Polarized: N; SizeAreaWB_mm2: 3; Value1: Unknown; U/M: EA; Value: 10pF; TaMax_C: 125°C; SizeZ_mm: 0.6; SizeX_mm: 1; SizeY_mm: 0.5; AEC Category: Q200
C28 C30 C47 = CMP-0006830-4: CAP, CERM, 0.22 uF, 16 V, +/- 10%, X7R, 0603; Manufacturer: Wurth Elektronik; TaMin_C: -55°C; Polarized: N; SizeAreaWB_mm2: 4.68; Value1: Unknown; U/M: EA; Value: 0.22uF; TaMax_C: 125°C; SizeZ_mm: 1; SizeX_mm: 1.6; SizeY_mm: 0.8; Cap_Case: 0603; SizeArea_mm2: 1.28; AEC Category: Q200
C29 = CMP-0097608-1: 0.47 µF ±10% 16V Ceramic Capacitor X7R 0603 (1608 Metric); Manufacturer: Wurth Electronics; AEC Qualified: No; Value: 470nF; TempCo: 15%; SizeZ_mm: 0.87mm
C31 = CMP-0097340-1: Alum. Polymer Cap 10µF 10V 5.5mmV-Chip WCAP-PSLP Series Lifetime 2000h +105°C; Manufacturer: Wurth Electronics; Life: 2000Hours; Dissipation Factor: 8%; Esr: 45m; IRMS_A: 1.2A; Tolerance_%: 20%; AEC Qualified: No; SizeZ_mm: 5.5mm; Leakage Current: 300uA
C35 C40 = CMP-0006831-4: CAP, CERM, 1 uF, 16 V, +/- 10%, X7R, 0603; Manufacturer: Wurth Elektronik; TaMin_C: -55°C; Polarized: N; SizeAreaWB_mm2: 4.68; Value1: Unknown; U/M: EA; Value: 1uF; TaMax_C: 125°C; SizeZ_mm: 1; SizeX_mm: 1.6; SizeY_mm: 0.8; SizeArea_mm2: 1.28; AEC Category: Q200
C37 C39 = CMP-0006828-4: CAP, CERM, 0.01 uF, 16 V, +/- 10%, X7R, 0603; Manufacturer: Wurth Elektronik; TaMin_C: -55°C; Polarized: N; SizeAreaWB_mm2: 4.68; Value1: Unknown; U/M: EA; Value: 0.01uF; TaMax_C: 125°C; SizeZ_mm: 1; SizeX_mm: 1.6; SizeY_mm: 0.8; SizeArea_mm2: 1.28; AEC Category: Q200
C38 = CMP-0006825-5: CAP, CERM, 2.2 uF, 16 V, +/- 20%, X5R, 0603; Manufacturer: Wurth Elektronik; TaMin_C: -55°C; Polarized: N; SizeAreaWB_mm2: 4.68; Value1: Unknown; U/M: EA; Value: 2.2uF; TaMax_C: 85°C; SizeZ_mm: 1; SizeX_mm: 1.6; SizeY_mm: 0.8; SizeArea_mm2: 1.28; Cap_F: 2.2µF; AEC Category: Q200
D1 = CMP-0002893-1: LED, Super Red, SMD; Manufacturer: Wurth Elektronik; Io_A: 20mA; Value1: W; U/M: EA; Vf_V: 1.9V; Type: AlInGaP
D2 = CMP-0002894-2: LED, Green, SMD; Manufacturer: Wurth Elektronik; Type: AlInGaP; Vf_V: 2V; Io_A: 20mA; Value1: W
J2 = CMP-0075483-1: as J1 on sheet MD089E1_DRV81xxx
J9 J10 = CMP-0086014-1: Header, 2.54mm, 7x2, Gold, TH; Manufacturer: Wurth Elektronik; Pitch_mm: 2.54; Voltage_V: 250V; Shrouded: N; Gender: Male; Current_A: 3A; Cert_UL: Y; Row_Count: 2
J11 = CMP-0097752-1: Conn Micro USB 2.0 Type AB RCP 5 POS 0.65mm Solder RA SMD 5 Terminal 1 Port T/R; Manufacturer: Wurth Electronics; Shrouded: true; Voltage_V: 30V; Usb Standard: USB 2.0; Current_A: 1A; ContactFinish: Gold; SizeZ_mm: 3.2mm; Is Female: yes; Conn Orientation: Horizontal; AEC Qualified: No
L1 L2 = CMP-0003184-2: Ferrite Bead, 140 ohm @ 100 MHz, 0.55 A, 0603; Manufacturer: Wurth Elektronik; Ztyp@1GHz_Ohm: 271.401; ZTyp@100MHz_Ohm: 140; SizeAreaWB_mm2: 4.68; DCR_ohm: 0.2; Value1: 0.2 ohm; Value: 140 ohm; Imax_A: 550mA; SizeZ_mm: 1; SizeX_mm: 1.6; SizeY_mm: 0.8; Value2: 0.55A; SizeArea_mm2: 1.28
R55 R60 = CMP-0026728-1: RES, 220 k, 1%, 0.0625 W, 0402; Manufacturer: Yageo America; Power_W: 62.5mW; TempCo: 100 ppm/C; U/M: EA; Value: 220k; SizeX_mm: 1; SizeY_mm: 0.5; SizeZ_mm: 0.6; AEC Qualified: N; VDC_V: 50V; AEC Category: Q200
R56 = CMP-0026190-2: RES, 240 k, 1%, 0.063 W, AEC-Q200 Grade 0, 0402; Manufacturer: Vishay-Dale; Power_W: 63mW; TempCo: 100 ppm/C; Value: 240k; SizeX_mm: 1; SizeY_mm: 0.5; SizeZ_mm: 0.6; Value2: 0.063W; AEC Qualified: Y; VDC_V: 50V; AEC Category: Q200; AEC Grade: 0
R57 = CMP-0026935-3: RES, 47 k, 5%, 0.063 W, AEC-Q200 Grade 0, 0402; Manufacturer: Vishay-Dale; Power_W: 63mW; TempCo: 200 ppm/C; Value_Code: 47k0; Value: 47k; EIA_Code: E24; SizeX_mm: 1; SizeY_mm: 0.5; SizeZ_mm: 0.6; Value2: 0.063W; AEC Qualified: Y; VDC_V: 50V; AEC Category: Q200; AEC Grade: 0
R58 = CMP-0025924-5: RES, 470, 5%, 0.1 W, 0603; Manufacturer: Yageo; Power_W: 100mW; TempCo: 100 ppm/C; Value_Code: 470R; Value: 470; EIA_Code: E24; SizeX_mm: 1.6; SizeY_mm: 0.8; SizeZ_mm: 1; Value2: 0.1W; SizeArea_mm2: 1.28; AEC Qualified: N; VDC_V: 75V; AEC Category: Q200; SizeAreaWB_mm2: 4.68
R59 = CMP-0025930-5: RES, 560, 5%, 0.1 W, 0603; Manufacturer: Yageo; Power_W: 100mW; TempCo: 100 ppm/C; Value_Code: 560R; Value: 560; EIA_Code: E24; SizeX_mm: 1.6; SizeY_mm: 0.8; SizeZ_mm: 1; Value2: 0.1W; SizeArea_mm2: 1.28; AEC Qualified: N; VDC_V: 75V; AEC Category: Q200; SizeAreaWB_mm2: 4.68
R61 = CMP-0026021-3: RES, 150 k, 1%, 0.063 W, AEC-Q200 Grade 0, 0402; Manufacturer: Vishay-Dale; Power_W: 63mW; TempCo: 100 ppm/C; Value: 150k; EIA_Code: E96; SizeX_mm: 1; SizeY_mm: 0.5; SizeZ_mm: 0.6; Value2: 0.063W; AEC Qualified: Y; VDC_V: 50V; AEC Category: Q200; AEC Grade: 0
R62 R63 R68 = CMP-0025697-4: as R3 on sheet MD089E1_DRV81xxx
R64-R67 = CMP-0097401-1: Thick Film Resistors 0402 10Ω ±1% 0.125W; Manufacturer: Wurth Electronics; TempCo: 100ppm/°C; VDC_V: 1.118V; Power_W: 125mW; AEC Qualified: No; SizeZ_mm: 0.4mm
R72 R75 = CMP-0026888-3: RES, 27, 5%, 0.063 W, AEC-Q200 Grade 0, 0402; Manufacturer: Vishay-Dale; Power_W: 63mW; TempCo: 200 ppm/C; Value_Code: 27R0; Value: 27; EIA_Code: E24; SizeX_mm: 1; SizeY_mm: 0.5; SizeZ_mm: 0.6; Value2: 0.063W; AEC Qualified: Y; VDC_V: 50V; AEC Category: Q200; AEC Grade: 0
R76 = CMP-0026085-3: RES, 1.40 k, 1%, 0.063 W, AEC-Q200 Grade 0, 0402; Manufacturer: Vishay-Dale; Power_W: 63mW; TempCo: 100 ppm/C; Value_Code: 1k40; Value: 1.40k; EIA_Code: E96; Res_ohm: 1.4k; SizeX_mm: 1; SizeY_mm: 0.5; SizeZ_mm: 0.6; Value2: 0.063W; AEC Qualified: Y; VDC_V: 50V; AEC Category: Q200; AEC Grade: 0
R77 = CMP-0026859-2: RES, 1.0 M, 5%, 0.063 W, AEC-Q200 Grade 0, 0402; Manufacturer: Vishay-Dale; Power_W: 63mW; TempCo: 200 ppm/C; Value_Code: 1M00; Value: 1.0Meg; EIA_Code: E24; Res_ohm: 1M; SizeX_mm: 1; SizeY_mm: 0.5; SizeZ_mm: 0.6; Value2: 0.063W; AEC Qualified: Y; VDC_V: 50V; AEC Category: Q200; AEC Grade: 0
R78 = CMP-0026907-3: RES, 33 k, 5%, 0.063 W, AEC-Q200 Grade 0, 0402; Manufacturer: Vishay-Dale; Power_W: 63mW; TempCo: 200 ppm/C; Value_Code: 33k0; Value: 33k; EIA_Code: E24; SizeX_mm: 1; SizeY_mm: 0.5; SizeZ_mm: 0.6; Value2: 0.063W; AEC Qualified: Y; VDC_V: 50V; AEC Category: Q200; AEC Grade: 0
SH-J22-SH-J29 SH-J31-SH-J35 = CMP-0003761-2: Shunt, 2.54mm, Gold, Black; Manufacturer: Wurth Elektronik
U2 = CMP-0039269-4: 16-Bit Ultra-Low-Power Microcontroller, 128KB Flash, 8KB RAM, USB, 12Bit ADC, 2 USCIs, 32Bit HW MPY, RGC0064B (VQFN-64); Alternate Manufacturer: Texas Instruments; Alternate PartNumber: MSP430F5528IRGCR; ADC: 12-bit SAR; ADC Channels: 16; Brown Out Reset: Yes; DMA: 3; Flash(KB): 128; Frequency(MHz): 25; GPIO: 47; Multiplier: 32x32; SRAM(B): 8192; Timers - 16-bit: 4; USB: 1; USCI_A (UART/LIN/IrDA/SPI): 2; Rating: Catalog; SizeArea_mm2: 81.0; SizeZ_mm: 1.0; Green_REACh: Passed; AEC Qualified: N; AEC Category: Q200; CompType: IC; Green_Lifecycle: Active; SizeY_mm: 9.0; SizeAreaWB_mm2: 121.0
U3 = CMP-0036328-3: 500mA, Adjustable, Low Quiescent Current, Low-Noise, High-PSRR, Single-Output LDO Regulator, DRB0008A (VSON-8); Manufacturer: Texas Instruments; CompType: IC; Green_Lifecycle: Active; SizeZ_mm: 1.0; Iq(Typ)(mA): 0.04; SizeY_mm: 3.0; SizeAreaWB_mm2: 16.0; SizeArea_mm2: 9.0; AEC Category: Q200; Vout Adj(Max)(V): 3.3; AEC Qualified: N; Accuracy(%): 2; Vin(Max)(V): 6.5; Vdo(Typ)(mV): 280; Iout(Max)(A): 0.5; Green_REACh: Passed; Rating: Catalog; Vin(Min)(V): 2.7
U6 = CMP-0043099-3: Low-Capacitance 2-Channel +/-15kV ESD Protection Array for High-Speed Data Interfaces, DRY0006A (USON-6); Manufacturer: Texas Instruments; IO Leakage Current(nA): 1; IEC 61000-4-2 Air-Gap(+/- kV): 15; USB High Speed: TRUE; IO Capacitance(Typ)(pF): 1.5; Eco-Plan: Green (RoHS & no Sb/Br); Breakdown Voltage(Min)(V): 11; IEC 61000-4-2 Contact(+/- kV): 8; AEC Category: Q200; AEC Qualified: N; CompType: IC; SizeAreaWB_mm2: 4.9; SizeArea_mm2: 1.45; SizeX_mm: 1.0; SizeZ_mm: 0.6; Rating: Catalog
Y1 = CMP-0085483-1: Oscillator, 4 MHz, 700 ppm, 39 pF, SMD; Manufacturer: MuRata; SizeArea_mm2: 9; Load Capacitance: 39 pF; SizeZ_mm: 1.2; AEC Category: Q200; Frequency Tolerance: 700 ppm; SizeX_mm: 4.5; SizeAreaWB_mm2: 16.5; TaMax_C: 85°C; TaMin_C: -20°C; SizeY_mm: 2; AEC Qualified: N; Frequency_Fixed: 4MHz

## Sheet MD089E1_Hardware.SchDoc
size A
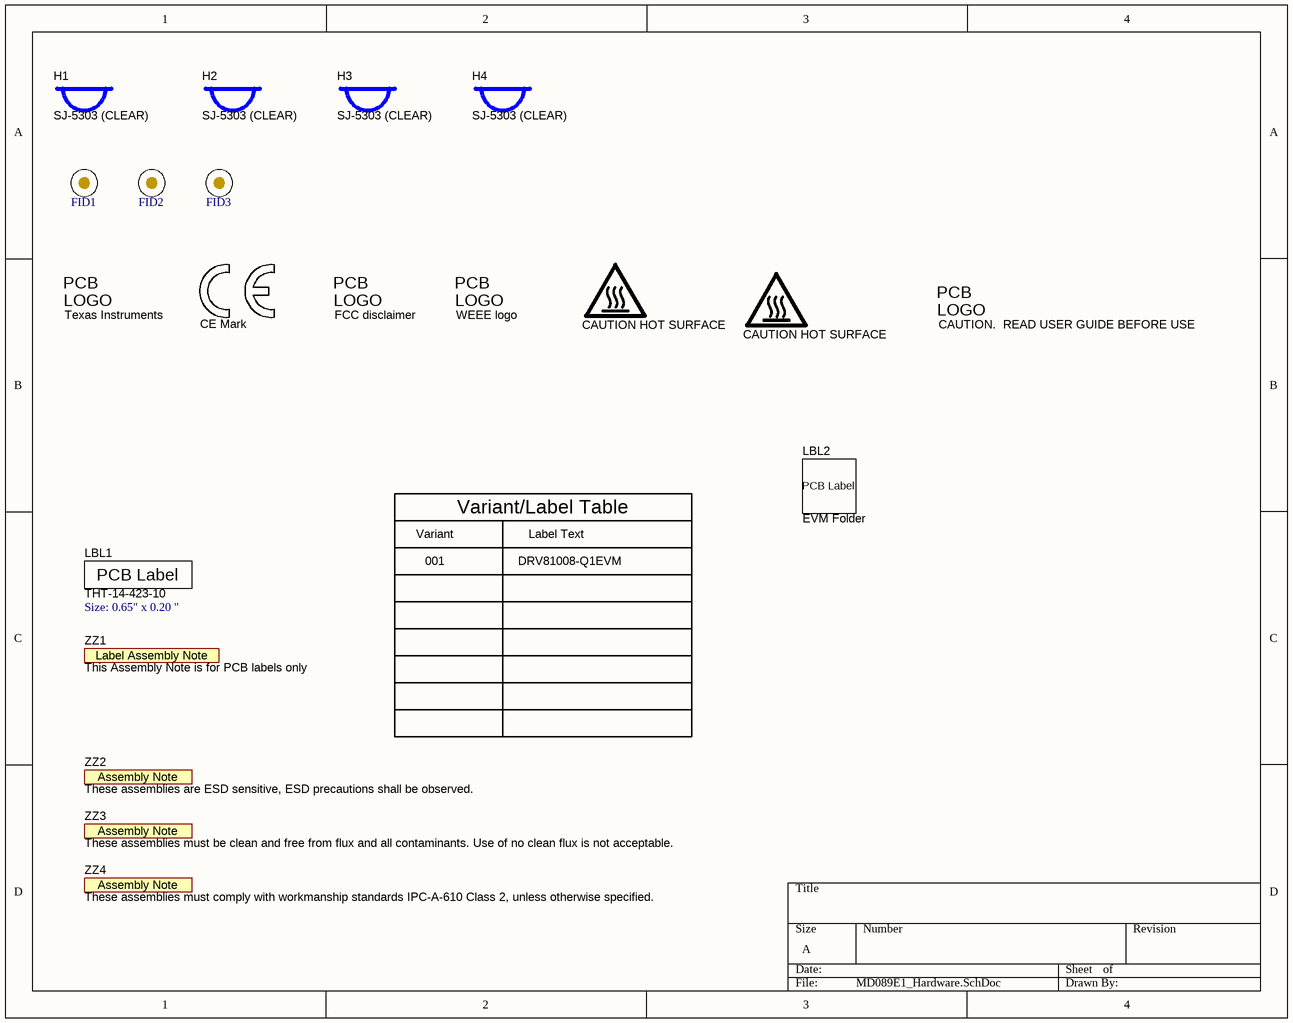
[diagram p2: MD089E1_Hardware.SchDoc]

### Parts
FID1  Fiducial  [Fiducial10-20]  (value not drawn)
FID2  Fiducial  [Fiducial10-20]  (value not drawn)
FID3  Fiducial  [Fiducial10-20]  (value not drawn)
H1  SJ-5303 (CLEAR)  [Bumpon_SJ5003Transparent]
H2  SJ-5303 (CLEAR)  [Bumpon_SJ5003Transparent]
H3  SJ-5303 (CLEAR)  [Bumpon_SJ5003Transparent]
H4  SJ-5303 (CLEAR)  [Bumpon_SJ5003Transparent]
LBL1  THT-14-423-10  Note: Size: 0.65" x 0.20 "  [Label_650x200]
LBL2  EVM Folder  [Label_375x375]
Logo1  CE Mark  [CE_Mark_5mm]  (no BOM)
Logo2  Texas Instruments  [TI_Stacked_Overlay_Small]  (no BOM)
Logo3  FCC disclaimer  [FCC_disclaimer]  (no BOM)
Logo4  WEEE logo  [WEEE_Minimum]  (no BOM)
Logo5  CAUTION.  READ USER GUIDE BEFORE USE  [IEC_Caution_Small]  (no BOM)
LOGO6  CAUTION HOT SURFACE  [IEC_HotSurface_Small]  (no BOM)
LOGO7  CAUTION HOT SURFACE  [IEC_HotSurface_Small]  (no BOM)
ZZ1  This Assembly Note is for PCB labels only  [AssemblyNoteLabel]  (no BOM)
ZZ2  These assemblies are ESD sensitive, ESD precautions shall be observed.  [AssemblyNote]  (no BOM)
ZZ3  These assemblies must be clean and free from flux and all contaminants. Use of no clean flux is not acceptable.  [AssemblyNote]  (no BOM)
ZZ4  These assemblies must comply with workmanship standards IPC-A-610 Class 2, unless otherwise specified.  [AssemblyNote]  (no BOM)

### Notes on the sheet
- Variant/Label Table
- Variant
- 001
- Label Text
- DRV81008-Q1EVM

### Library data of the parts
FID1-FID3 = CMP-0077181-1: Fiducial mark.  There is nothing to buy or mount.
H1-H4 = CMP-0003620-1: Bumpon, Hemisphere, 0.44 X 0.20, Clear; Manufacturer: 3M
LBL1 = CMP-0003625-1: Thermal Transfer Printable Labels, 0.650" W x 0.200" H - 10,000 per roll; Manufacturer: Brady
LBL2 = CMP-00007-1: Harsh Environment Multi-Purpose Polyester Labels for 3" Core Printers - 0.375" x 0.375", White; Manufacturer: Brady; PartNumber: THT-14-423-10; Body Material: PET,Polyester; Note: Size: 0.375" x 0.375"
Logo1 = CMP-0074844-1: SymbolCreator: a0412235
Logo2 = CMP-0074838-1: Texas Instrument Corporate Signature; SymbolCreator: a0412235; Lib Reference: TI_Logo
Logo3 = CMP-0074847-1: FCC_disclaimer
Logo4 = CMP-0074769-3: Manufacturer: Texas Instruments; CompType: IC; AEC Category: Q200
Logo5 = CMP-0074836-1: IEC 61010-1 Caution Warning; SymbolCreator: a0412235; Lib Reference: IEC_Caution
LOGO6 LOGO7 = CMP-0074837-2: IEC 61010-1 Hot Surface Warning; Manufacturer: Texas Instruments; SymbolCreator: a0412235; CompType: IC; AEC Category: Q200
ZZ1 = CMP-0003616-3
ZZ2 = CMP-0077236-1
ZZ3 = CMP-0077237-1
ZZ4 = CMP-0077238-1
